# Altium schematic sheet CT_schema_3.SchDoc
size 287 x 169 mm
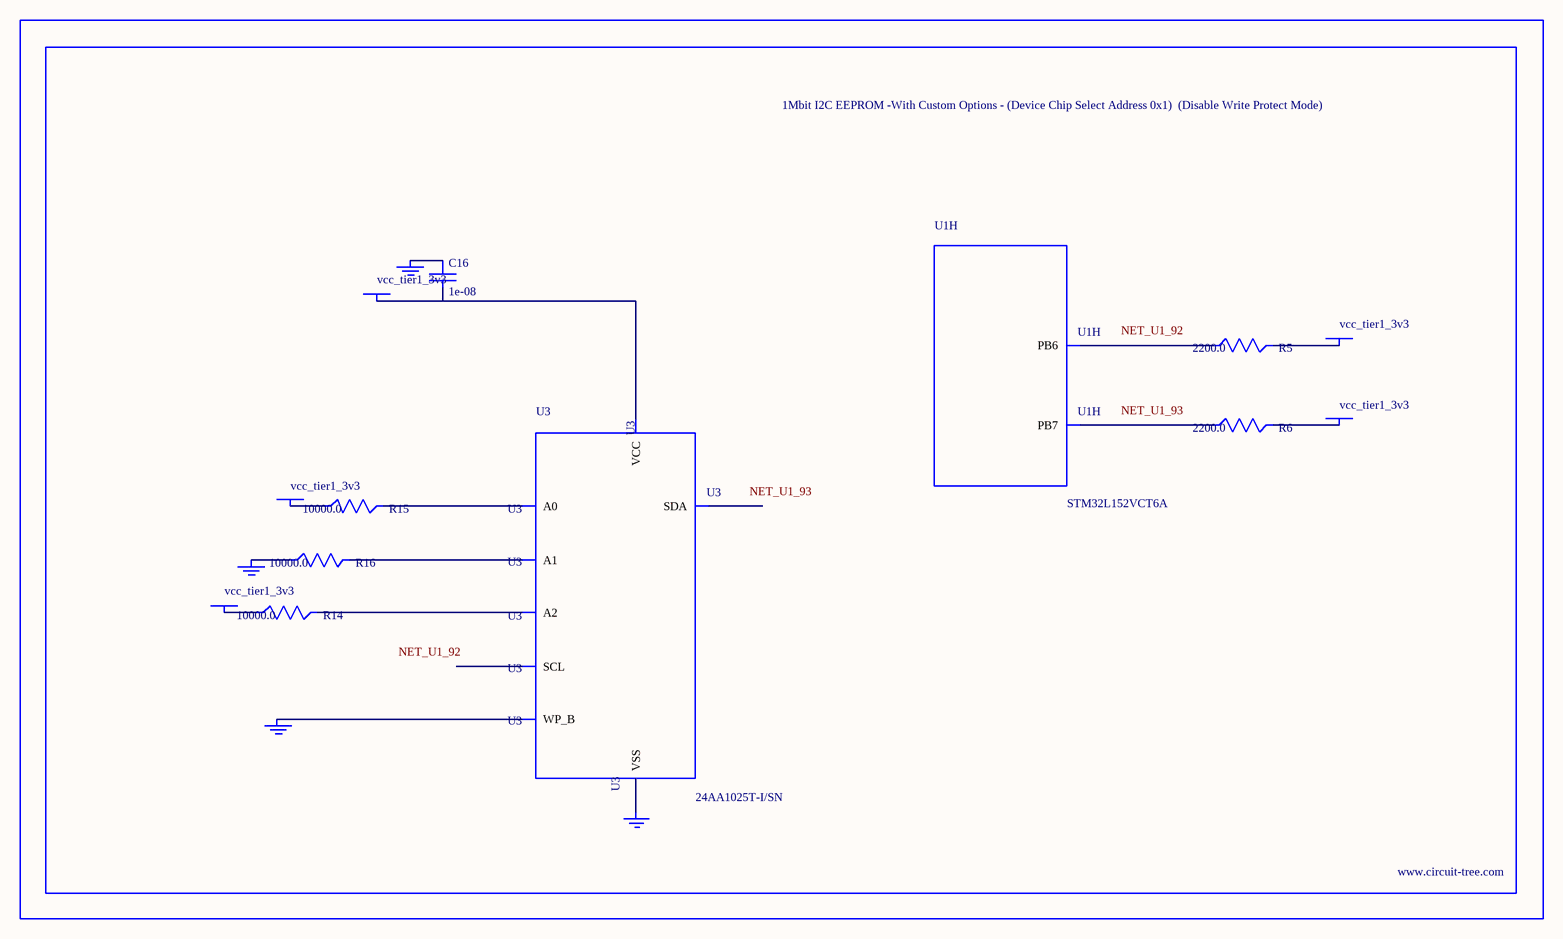
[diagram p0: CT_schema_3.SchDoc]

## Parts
BORDER2  (no value)
C16  1e-08  [C0402]
GND_INSTANCE_2_0  (no value)
GND_INSTANCE_2_1  (no value)
GND_INSTANCE_2_2  (no value)
GND_INSTANCE_2_3  (no value)
POWER_INSTANCE_2_0  vcc_tier1_3v3
POWER_INSTANCE_2_1  vcc_tier1_3v3
POWER_INSTANCE_2_2  vcc_tier1_3v3
POWER_INSTANCE_2_3  vcc_tier1_3v3
POWER_INSTANCE_2_4  vcc_tier1_3v3
R5  2200.0  [R0603]
R6  2200.0  [R0603]
R14  10000.0  [R0603]
R15  10000.0  [R0603]
R16  10000.0  [R0603]
U1  STM32L152VCT6A  [LQFP100]  (part H of 9)
U3  24AA1025T-I/SN  [SOIC-8]

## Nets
NetC16_1: C16.1 GND_INSTANCE_2_2.0(GND)
NetC16_2: C16.2 POWER_INSTANCE_2_2.0(PWR) U3.8(VCC)
NetGND_INSTANCE_2_0_0: GND_INSTANCE_2_0.0(GND) R16.1
NetGND_INSTANCE_2_1_0: GND_INSTANCE_2_1.0(GND) U3.7(WP_B)
NetGND_INSTANCE_2_3_0: GND_INSTANCE_2_3.0(GND) U3.4(VSS)
NetPOWER_INSTANCE_2_0_0: POWER_INSTANCE_2_0.0(PWR) R15.1
NetPOWER_INSTANCE_2_1_0: POWER_INSTANCE_2_1.0(PWR) R14.1
NetPOWER_INSTANCE_2_3_0: POWER_INSTANCE_2_3.0(PWR) R5.2
NetPOWER_INSTANCE_2_4_0: POWER_INSTANCE_2_4.0(PWR) R6.2
NetR5_1: R5.1 U1.92(PB6)
NetR6_1: R6.1 U1.93(PB7)
NetR14_2: R14.2 U3.3(A2)
NetR15_2: R15.2 U3.1(A0)
NetR16_2: R16.2 U3.2(A1)

Not connected (* = marked no-connect by the designer): U3 5(SDA) 6(SCL)

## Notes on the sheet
- Labels drawn without touching a wire or pin: NET_U1_92, NET_U1_93

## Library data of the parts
BORDER2 = BORDER_PAGE2
C16 = C0402C103K3RAC
GND_INSTANCE_2_0-GND_INSTANCE_2_3 = GND
POWER_INSTANCE_2_0-POWER_INSTANCE_2_4 = PWR
R5 R6 = RC0603JR-072K2L
R14-R16 = RC0603JR-0710KL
